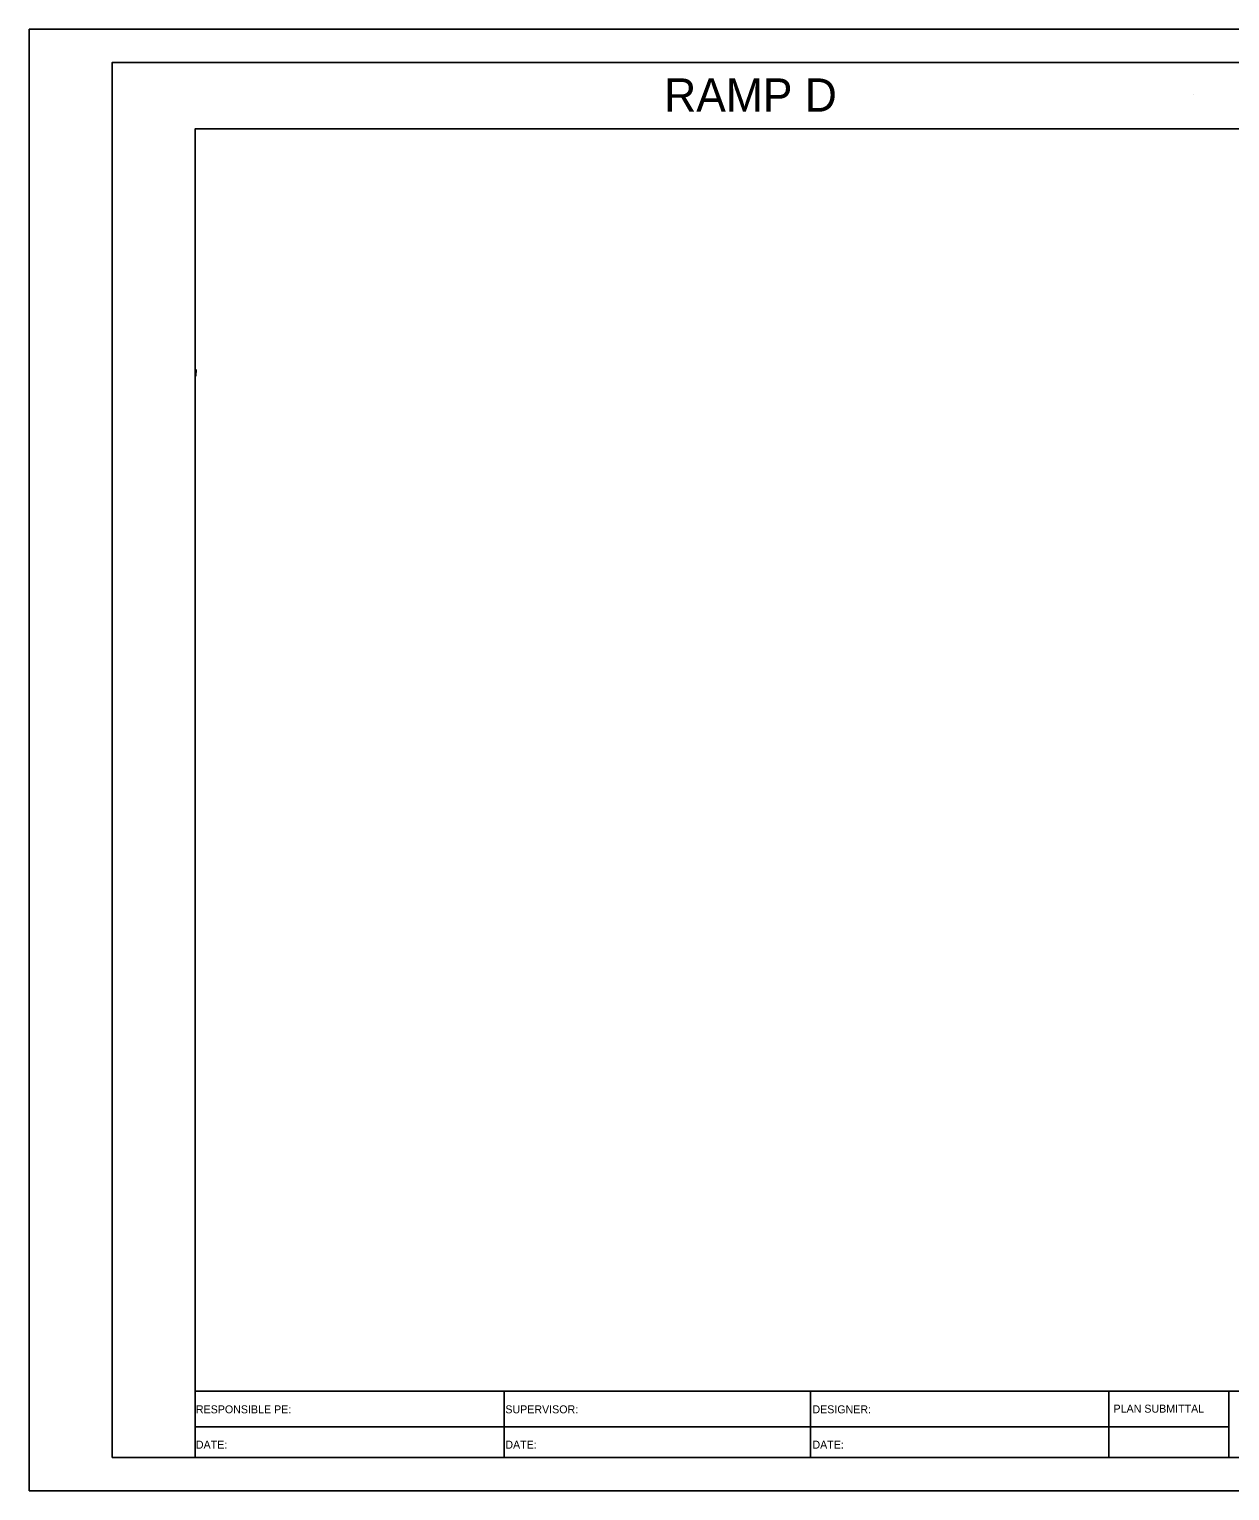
# Model space of a CAD drawing. Extents: x 1797478 to 1804836, y 246529 to 250952.
# Drawn here: x 1802116 to 1802296.8, y 250064.4 to 250284.4 of the extents above; entities that cross this region are included whole.
import ezdxf

# ---------------------------------------------------------------- set-up
doc = ezdxf.new("R2010")
doc.units = 0
for name, color, linetype in [('2', 7, 'Continuous'), ('ANNO-SHT', 7, 'Continuous'), ('ANNO-TXT', 7, 'Continuous'), ('AXIS', 7, 'Continuous'), ('DRAINAGE', 7, 'Continuous'), ('Level 1', 7, 'Continuous'), ('Level 62', 7, 'Continuous'), ('SHT-BDR', 7, 'Continuous'), ('SHT-BNDRY', 7, 'Continuous')]:
    doc.layers.add(name, color=color, linetype=linetype)

# ---------------------------------------------------------------- blocks, each defined once
blk = doc.blocks.new('SC47208')
at = {"layer": 'Level 1'}
blk.add_line((0, 0), (0, 0), dxfattribs=at)

msp = doc.modelspace()

# ---------------------------------------------------------------- linework, layer by layer
at = {"layer": '2'}
msp.add_lwpolyline([(1802141.12, 250233.21), (1802141.1, 250232.21)], dxfattribs=at)
msp.add_lwpolyline([(1802141.12, 250233.21), (1802141.1, 250232.21)], dxfattribs=at)
at = {"layer": 'AXIS'}
msp.add_line((1802141, 250189.42), (1802141, 250189.43), dxfattribs=at)
at = {"layer": 'Level 62'}
msp.add_lwpolyline([(1802116, 250064.42), (1802456, 250064.42), (1802456, 250284.42), (1802116, 250284.42)], close=True, dxfattribs=at)
at = {"layer": 'SHT-BDR'}
msp.add_lwpolyline([(1802141, 250079.43), (1802441, 250079.43), (1802441, 250269.43), (1802141, 250269.43)], close=True, dxfattribs=at)
at = {"layer": 'SHT-BNDRY'}
for p, q in [((1802141, 250069.42), (1802141, 250079.43)), ((1802187.52, 250079.43), (1802187.52, 250069.42)), ((1802233.67, 250069.42), (1802233.67, 250079.43)), ((1802278.59, 250069.42), (1802278.59, 250079.43)), ((1802296.63, 250069.42), (1802296.63, 250079.43)), ((1802141, 250074.03), (1802296.63, 250074.03))]:
    msp.add_line(p, q, dxfattribs=at)
msp.add_lwpolyline([(1802128.5, 250069.42), (1802451, 250069.42), (1802451, 250279.42), (1802128.5, 250279.42)], close=True, dxfattribs=at)

# ---------------------------------------------------------------- block references
at = {"layer": 'DRAINAGE', "xscale": 0.2, "yscale": 0.20000000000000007, "rotation": -116.41666666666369}
msp.add_blockref('SC47208', (1802291.32, 250274.62), dxfattribs=at)
msp.add_blockref('SC47208', (1802291.32, 250274.62), dxfattribs=at)

# ---------------------------------------------------------------- texts
at = {"layer": 'ANNO-SHT'}
msp.add_text('                 RAMP D                 ', height=4.9995, rotation=360, dxfattribs=at).set_placement((1802180.04, 250272.02))
at = {"layer": 'ANNO-TXT'}
for s, p in [('RESPONSIBLE PE:', (1802141.1, 250076.08)), ('SUPERVISOR:', (1802187.7, 250076.08)), ('DESIGNER:', (1802233.94, 250076.08)), ('PLAN SUBMITTAL', (1802279.28, 250076.18)), ('DATE:', (1802141.1, 250070.76)), ('DATE:', (1802187.7, 250070.76)), ('DATE:', (1802233.94, 250070.76))]:
    msp.add_text(s, height=1.2, rotation=360, dxfattribs=at).set_placement(p)

doc.saveas('drawing.dxf')
